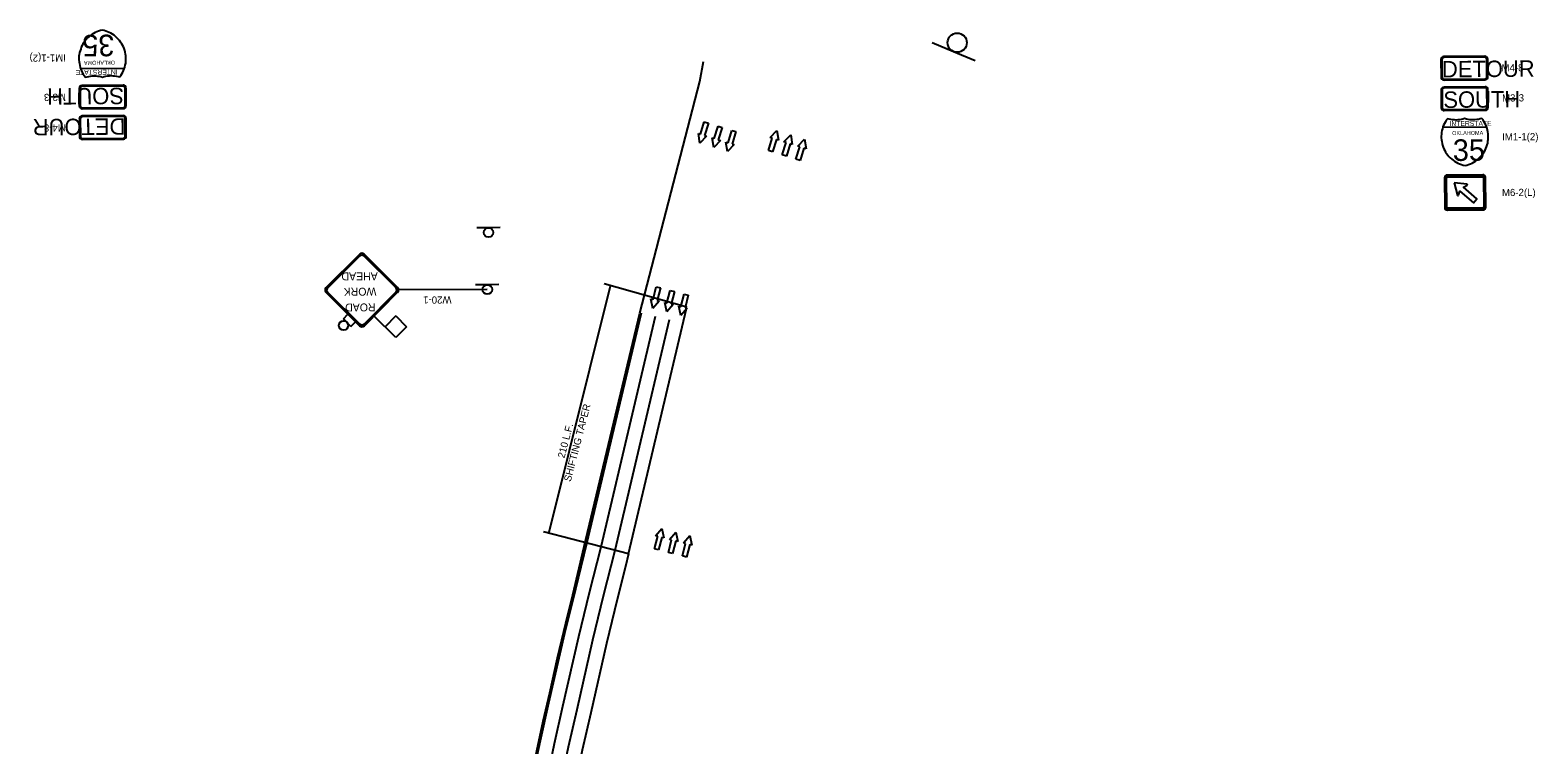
# Model space of a CAD drawing. Extents: x 2135767 to 2151731, y 141839 to 175894.
# Drawn here: x 2150475 to 2151731, y 147612 to 148208 of the extents above; entities that cross this region are included whole.
import ezdxf

# ---------------------------------------------------------------- set-up
doc = ezdxf.new("R2010")
doc.units = 0
for name, color, linetype in [('PR_Dimensions_Phase1', 7, 'Continuous'), ('PR_Phasing_Detour_1', 7, 'Continuous'), ('PR_Phasing_Traffic_Control_Devices_1', 7, 'Continuous'), ('PR_Phasing_Traffic_Striping_Dashed_Phase_1', 7, 'Continuous'), ('PR_Phasing_Traffic_Striping_White_Phase_1', 7, 'Continuous'), ('PR_Phasing_Traffic_Striping_Yellow_Phase_1', 7, 'Continuous'), ('Pr_Traffic_Arrows_Phase_1', 7, 'Continuous'), ('PR_Traffic_Striping_White_Temp', 7, 'Continuous'), ('PR_Txt', 7, 'Continuous'), ('PR_Txt_Phase_1', 7, 'Continuous')]:
    doc.layers.add(name, color=color, linetype=linetype)

# ---------------------------------------------------------------- blocks, each defined once
blk = doc.blocks.new('FLSHFLAG')
at = {"layer": 'PR_Txt'}
for p, q in [((-1.2, 14.13), (0.84, 16.15)), ((0.84, 16.15), (4.9, 12.08)), ((0.82, 12.08), (-1.2, 14.13)), ((0.82, 12.08), (2.86, 14.11)), ((9.26, 14), (8.4, 13.15)), ((9.26, 14), (10.68, 12.58)), ((10.68, 12.58), (9.83, 11.72))]:
    blk.add_line(p, q, dxfattribs=at)
blk.add_circle((10.65, 13.84), 0.873, dxfattribs=at)

msp = doc.modelspace()

# ---------------------------------------------------------------- linework, layer by layer
at = {"layer": 'PR_Dimensions_Phase1'}
for p, q in [((2150855.9, 147991.6), (2150782, 147991.3)), ((2150907.1, 147788.3), (2150958.6, 147994.6)), ((2151022.3, 147976.8), (2150953.3, 147996.3)), ((2150973.7, 147771.4), (2150902.7, 147789.6))]:
    msp.add_line(p, q, dxfattribs=at)
at = {"layer": 'PR_Phasing_Detour_1'}
for p, q in [((2151226.6, 148197.3), (2151244.5, 148189.9)), ((2151244.5, 148189.9), (2151262.3, 148182.5)), ((2151650.5, 148183.2), (2151650.6, 148168.6)), ((2151651.3, 148183.2), (2151651.4, 148168.6)), ((2151687.1, 148186), (2151652.9, 148185.7)), ((2151687.1, 148185.2), (2151652.9, 148184.9)), ((2151688.9, 148168.9), (2151688.8, 148183.5)), ((2151689.7, 148168.9), (2151689.6, 148183.5)), ((2150553.9, 148175.9), (2150516.7, 148175.6)), ((2151653.1, 148167), (2151687.3, 148167.2)), ((2151653.1, 148166.2), (2151687.3, 148166.4)), ((2150515.8, 148159.2), (2150515.9, 148144.5)), ((2150516.6, 148159.2), (2150516.8, 148144.5)), ((2150552.4, 148161.9), (2150518.2, 148161.7)), ((2150552.4, 148161.1), (2150518.3, 148160.8)), ((2150554.2, 148144.8), (2150554.1, 148159.5)), ((2150555, 148144.9), (2150554.9, 148159.5)), ((2151650.6, 148157.8), (2151650.8, 148143.1)), ((2151651.5, 148157.8), (2151651.6, 148143.1)), ((2151687.3, 148160.5), (2151653.1, 148160.2)), ((2151687.3, 148159.7), (2151653.1, 148159.4)), ((2151689, 148143.4), (2151688.9, 148158.1)), ((2151689.8, 148143.4), (2151689.7, 148158.1)), ((2150518.4, 148142.9), (2150552.6, 148143.2)), ((2150518.4, 148142.1), (2150552.6, 148142.4)), ((2151653.2, 148141.5), (2151687.4, 148141.8)), ((2151653.2, 148140.7), (2151687.4, 148141)), ((2150516, 148133.7), (2150516.1, 148119.1)), ((2150516.8, 148133.7), (2150516.9, 148119.1)), ((2150552.6, 148136.5), (2150518.4, 148136.2)), ((2150552.6, 148135.7), (2150518.4, 148135.4)), ((2150554.3, 148119.4), (2150554.2, 148134)), ((2150555.1, 148119.4), (2150555, 148134)), ((2151651.8, 148126.8), (2151689, 148127.1)), ((2150518.5, 148117.5), (2150552.7, 148117.7)), ((2150518.5, 148116.7), (2150552.7, 148116.9)), ((2151653.5, 148084.8), (2151653.7, 148059.8)), ((2151654.1, 148084.8), (2151654.3, 148059.8)), ((2151654.1, 148084.8), (2151654.3, 148059.8)), ((2151655.4, 148059.9), (2151655.2, 148084.8)), ((2151655.4, 148059.9), (2151655.2, 148084.8)), ((2151685.5, 148087.2), (2151655.7, 148087)), ((2151685.5, 148086.6), (2151655.7, 148086.4)), ((2151685.5, 148086.6), (2151655.7, 148086.4)), ((2151655.7, 148085.4), (2151685.5, 148085.6)), ((2151655.7, 148085.4), (2151685.5, 148085.6)), ((2151672.4, 148079.5), (2151661.5, 148080.6)), ((2151661.5, 148080.6), (2151664.2, 148070)), ((2151686.1, 148085.1), (2151686.3, 148060.1)), ((2151686.1, 148085.1), (2151686.3, 148060.1)), ((2151687.3, 148060.1), (2151687.1, 148085.1)), ((2151687.3, 148060.1), (2151687.1, 148085.1)), ((2151687.9, 148060.1), (2151687.7, 148085.1)), ((2151685.8, 148059.6), (2151655.9, 148059.3)), ((2151685.8, 148059.6), (2151655.9, 148059.3)), ((2151655.9, 148058.3), (2151685.8, 148058.5)), ((2151655.9, 148058.3), (2151685.8, 148058.5)), ((2151655.9, 148057.7), (2151685.8, 148057.9)), ((2150856.9, 148043.1), (2150847.3, 148043.1)), ((2150866.6, 148043.2), (2150856.9, 148043.1))]:
    msp.add_line(p, q, dxfattribs=at)
for points in [[(2150549.7, 148168.8), (2150550.6, 148170), (2150551.5, 148171.3), (2150552.2, 148172.7), (2150552.9, 148174.1), (2150553.4, 148175.6), (2150553.9, 148177), (2150554.3, 148178.6), (2150554.6, 148180.1), (2150554.8, 148181.6), (2150554.8, 148183.2), (2150554.8, 148184.7), (2150554.7, 148186.3), (2150554.5, 148187.8), (2150554.2, 148189.4), (2150553.8, 148190.9), (2150553.3, 148192.3), (2150552.7, 148193.8), (2150552, 148195.2), (2150551.2, 148196.5), (2150550.4, 148197.8), (2150549.4, 148199.1), (2150548.4, 148200.3), (2150547.3, 148201.4), (2150546.2, 148202.4), (2150544.9, 148203.4), (2150543.7, 148204.3), (2150542.3, 148205.1), (2150540.9, 148205.8), (2150539.5, 148206.4), (2150538.1, 148206.9), (2150536.6, 148207.4), (2150535, 148207.7), (2150533.5, 148207.3), (2150532, 148206.9), (2150530.6, 148206.3), (2150529.2, 148205.7), (2150527.8, 148204.9), (2150526.5, 148204.1), (2150525.2, 148203.2), (2150524, 148202.2), (2150522.9, 148201.2), (2150521.8, 148200), (2150520.8, 148198.8), (2150519.9, 148197.6), (2150519, 148196.3), (2150518.3, 148194.9), (2150517.6, 148193.5), (2150517.1, 148192), (2150516.6, 148190.6), (2150516.2, 148189.1), (2150515.9, 148187.5), (2150515.7, 148186), (2150515.6, 148184.4), (2150515.6, 148182.9), (2150515.8, 148181.3), (2150516, 148179.8), (2150516.3, 148178.2), (2150516.7, 148176.7), (2150517.2, 148175.3), (2150517.8, 148173.8), (2150518.4, 148172.4), (2150519.2, 148171.1), (2150520.1, 148169.8), (2150521, 148168.5), (2150522.4, 148168.9), (2150523.8, 148169.2), (2150525.3, 148169.5), (2150526.7, 148169.6), (2150528.2, 148169.7), (2150529.6, 148169.6), (2150531.1, 148169.5), (2150532.5, 148169.3), (2150534, 148169), (2150535.4, 148168.6), (2150536.8, 148169), (2150538.2, 148169.4), (2150539.6, 148169.6), (2150541.1, 148169.7), (2150542.5, 148169.8), (2150544, 148169.7), (2150545.4, 148169.6), (2150546.9, 148169.4), (2150548.3, 148169.1), (2150549.7, 148168.8)], [(2151655.9, 148133.9), (2151655, 148132.6), (2151654.2, 148131.3), (2151653.4, 148129.9), (2151652.8, 148128.5), (2151652.2, 148127.1), (2151651.7, 148125.6), (2151651.4, 148124.1), (2151651.1, 148122.5), (2151650.9, 148121), (2151650.8, 148119.4), (2151650.8, 148117.9), (2151650.9, 148116.3), (2151651.2, 148114.8), (2151651.5, 148113.3), (2151651.9, 148111.8), (2151652.4, 148110.3), (2151653, 148108.8), (2151653.7, 148107.4), (2151654.4, 148106.1), (2151655.3, 148104.8), (2151656.2, 148103.6), (2151657.2, 148102.4), (2151658.3, 148101.3), (2151659.5, 148100.2), (2151660.7, 148099.3), (2151662, 148098.4), (2151663.3, 148097.6), (2151664.7, 148096.9), (2151666.1, 148096.2), (2151667.6, 148095.7), (2151669.1, 148095.3), (2151670.6, 148094.9), (2151672.1, 148095.3), (2151673.6, 148095.7), (2151675.1, 148096.3), (2151676.5, 148096.9), (2151677.9, 148097.7), (2151679.2, 148098.5), (2151680.4, 148099.4), (2151681.6, 148100.4), (2151682.8, 148101.5), (2151683.9, 148102.6), (2151684.9, 148103.8), (2151685.8, 148105), (2151686.6, 148106.4), (2151687.4, 148107.7), (2151688, 148109.1), (2151688.6, 148110.6), (2151689.1, 148112.1), (2151689.5, 148113.6), (2151689.7, 148115.1), (2151689.9, 148116.6), (2151690, 148118.2), (2151690, 148119.8), (2151689.9, 148121.3), (2151689.7, 148122.9), (2151689.4, 148124.4), (2151689, 148125.9), (2151688.5, 148127.4), (2151687.9, 148128.8), (2151687.2, 148130.2), (2151686.4, 148131.5), (2151685.6, 148132.9), (2151684.7, 148134.1), (2151683.2, 148133.7), (2151681.8, 148133.4), (2151680.4, 148133.2), (2151678.9, 148133), (2151677.5, 148133), (2151676, 148133), (2151674.6, 148133.1), (2151673.1, 148133.3), (2151671.7, 148133.6), (2151670.3, 148134), (2151668.9, 148133.6), (2151667.5, 148133.3), (2151666, 148133), (2151664.6, 148132.9), (2151663.1, 148132.8), (2151661.7, 148132.9), (2151660.2, 148133), (2151658.8, 148133.2), (2151657.4, 148133.5), (2151655.9, 148133.9)], [(2151661.5, 148080.6), (2151664.2, 148070)], [(2151672.4, 148079.5), (2151661.5, 148080.6)], [(2151665.2, 148070.1), (2151666.4, 148073.6), (2151677.7, 148063.9), (2151680.4, 148067.1), (2151669.2, 148076.8), (2151672.5, 148078.5)], [(2151665.2, 148070.1), (2151666.4, 148073.6), (2151677.7, 148063.9), (2151680.4, 148067.1), (2151669.2, 148076.8), (2151672.5, 148078.5)]]:
    msp.add_lwpolyline(points, dxfattribs=at)
for centre, radius in [((2151247.5, 148197.3), 8), ((2150856.9, 148039.1), 4)]:
    msp.add_circle(centre, radius, dxfattribs=at)
for centre, radius, start, end in [((2151653, 148183.2), 2.44, 90.4611, 180.4611), ((2151653, 148183.2), 1.63, 90.4611, 180.4611), ((2151687.1, 148183.5), 2.44, 0.4611, 90.4611), ((2151687.1, 148183.5), 1.63, 0.4611, 90.4611), ((2151653.1, 148168.6), 2.44, 180.4611, 270.4611), ((2151653.1, 148168.6), 1.63, 180.4611, 270.4611), ((2151687.3, 148168.9), 2.44, 270.4611, 0.4611), ((2151687.3, 148168.9), 1.63, 270.4611, 0.4611), ((2150518.3, 148159.2), 2.44, 90.4611, 180.4611), ((2150518.3, 148159.2), 1.63, 90.4611, 180.4611), ((2150552.5, 148159.5), 2.44, 0.4611, 90.4611), ((2150552.5, 148159.5), 1.63, 0.4611, 90.4611), ((2151653.1, 148157.8), 2.44, 90.4611, 180.4611), ((2151653.1, 148157.8), 1.63, 90.4611, 180.4611), ((2151687.3, 148158.1), 2.44, 0.4611, 90.4611), ((2151687.3, 148158.1), 1.63, 0.4611, 90.4611), ((2150518.4, 148144.6), 2.44, 180.4611, 270.4611), ((2150518.4, 148144.6), 1.63, 180.4611, 270.4611), ((2150552.6, 148144.8), 2.44, 270.4611, 0.4611), ((2150552.6, 148144.8), 1.63, 270.4611, 0.4611), ((2151653.2, 148143.1), 2.44, 180.4611, 270.4611), ((2151653.2, 148143.1), 1.63, 180.4611, 270.4611), ((2151687.4, 148143.4), 1.63, 270.4611, 0.4611), ((2151687.4, 148143.4), 2.44, 270.4611, 0.4611), ((2150518.4, 148133.8), 2.44, 90.4611, 180.4611), ((2150518.4, 148133.8), 1.63, 90.4611, 180.4611), ((2150552.6, 148134), 2.44, 0.4611, 90.4611), ((2150552.6, 148134), 1.63, 0.4611, 90.4611), ((2150518.5, 148119.1), 2.44, 180.4611, 270.4611), ((2150518.5, 148119.1), 1.63, 180.4611, 270.4611), ((2150552.7, 148119.4), 2.44, 270.4611, 0.4611), ((2150552.7, 148119.4), 1.63, 270.4611, 0.4611), ((2151655.7, 148084.8), 2.16, 90.4611, 180.4611), ((2151655.7, 148084.8), 1.55, 90.4611, 180.4611), ((2151655.7, 148084.8), 1.55, 90.4611, 180.4611), ((2151655.7, 148084.8), 0.537, 90.4611, 180.4611), ((2151655.7, 148084.8), 0.537, 90.4611, 180.4611), ((2151671.9, 148078.9), 0.694, 319.2024, 49.2024), ((2151671.9, 148078.9), 0.694, 319.2024, 49.2024), ((2151685.5, 148085.1), 2.16, 0.4611, 90.4611), ((2151685.5, 148085.1), 1.55, 0.4611, 90.4611), ((2151685.5, 148085.1), 1.55, 0.4611, 90.4611), ((2151685.5, 148085.1), 0.537, 0.4611, 90.4611), ((2151685.5, 148085.1), 0.537, 0.4611, 90.4611), ((2151664.7, 148070.5), 0.694, 229.2024, 319.2024), ((2151664.7, 148070.5), 0.694, 229.2024, 319.2024), ((2151655.9, 148059.9), 2.16, 180.4611, 270.4611), ((2151655.9, 148059.9), 1.55, 180.4611, 270.4611), ((2151655.9, 148059.9), 1.55, 180.4611, 270.4611), ((2151655.9, 148059.9), 0.537, 180.4611, 270.4611), ((2151655.9, 148059.9), 0.537, 180.4611, 270.4611), ((2151685.7, 148060.1), 2.16, 270.4611, 0.4611), ((2151685.7, 148060.1), 1.55, 270.4611, 0.4611), ((2151685.7, 148060.1), 0.537, 270.4611, 0.4611), ((2151685.7, 148060.1), 1.55, 270.4611, 0.4611), ((2151685.7, 148060.1), 0.537, 270.4611, 0.4611)]:
    msp.add_arc(centre, radius, start, end, dxfattribs=at)
at = {"layer": 'PR_Phasing_Traffic_Control_Devices_1'}
for p, q in [((2150749.3, 148020.9), (2150721.5, 147993)), ((2150749.3, 148019.4), (2150723.1, 147993)), ((2150781.2, 147993.2), (2150753.2, 148021)), ((2150779.6, 147993.2), (2150753.2, 148019.4)), ((2150721.6, 147989), (2150749.5, 147961.3)), ((2150723.1, 147989), (2150749.5, 147962.9)), ((2150753.5, 147962.9), (2150779.6, 147989.3)), ((2150753.5, 147961.3), (2150781.2, 147989.3)), ((2150855.9, 147995.6), (2150846.2, 147995.6)), ((2150865.5, 147995.7), (2150855.9, 147995.6))]:
    msp.add_line(p, q, dxfattribs=at)
msp.add_circle((2150855.9, 147991.6), 4, dxfattribs=at)
for centre, start, end in [((2150751.3, 148019), 45.2355, 135.2355), ((2150751.3, 148017.4), 45.2355, 135.2355), ((2150723.5, 147991), 135.2355, 225.2355), ((2150725.1, 147991), 135.2355, 225.2355), ((2150777.6, 147991.2), 315.2355, 45.2355), ((2150779.2, 147991.2), 315.2355, 45.2355), ((2150751.5, 147964.9), 225.2355, 315.2355), ((2150751.5, 147963.3), 225.2355, 315.2355)]:
    msp.add_arc(centre, 2.81, start, end, dxfattribs=at)
at = {"layer": 'PR_Phasing_Traffic_Striping_Dashed_Phase_1'}
for points in [[(2150995.7, 147969.1), (2150950.4, 147776.9), (2150940.9, 147739), (2150932, 147702.1), (2150918.7, 147644.1), (2150911.7, 147613), (2150905.4, 147583.6), (2150886.7, 147494.2), (2150864.4, 147373), (2150848.5, 147279.4), (2150835.2, 147193.6), (2150823.3, 147104.9), (2150811.3, 147007.2), (2150800.8, 146902.2)], [(2151007.4, 147966.3), (2150962.1, 147774.1), (2150952.6, 147736.2), (2150943.6, 147699.4), (2150930.4, 147641.4), (2150923.4, 147610.4), (2150917.1, 147581.2), (2150898.5, 147491.9), (2150876.2, 147370.9), (2150860.4, 147277.4), (2150847.1, 147191.9), (2150835.2, 147103.3), (2150823.2, 147005.9), (2150812.7, 146901.1)]]:
    msp.add_lwpolyline(points, dxfattribs=at)
at = {"layer": 'PR_Phasing_Traffic_Striping_White_Phase_1'}
msp.add_lwpolyline([(2150844.1, 147330.9), (2150854.8, 147392.4), (2150859.3, 147416.9), (2150869.3, 147471.3), (2150885.1, 147550.1), (2150891.1, 147578.7), (2150902.6, 147631.8), (2150907.9, 147655.6), (2150914.5, 147684.7), (2150921.4, 147713.7), (2150927.1, 147737.3), (2150936.7, 147777.6), (2150983.1, 147972), (2151033, 148164.9), (2151036.1, 148181.7)], dxfattribs=at)
at = {"layer": 'PR_Phasing_Traffic_Striping_Yellow_Phase_1'}
msp.add_line((2150973.7, 147771.4), (2151022, 147975.8), dxfattribs=at)
msp.add_lwpolyline([(2150973.7, 147771.4), (2150971.1, 147760.7), (2150964.2, 147733.3), (2150955.3, 147696.6), (2150942.1, 147638.8), (2150935.1, 147607.9), (2150928.8, 147578.7), (2150910.3, 147489.6), (2150888, 147368.8), (2150872.2, 147275.5), (2150858.9, 147190.1), (2150847.1, 147101.8), (2150835.1, 147004.6), (2150824.7, 146899.9)], dxfattribs=at)
at = {"layer": 'Pr_Traffic_Arrows_Phase_1'}
for p, q in [((2151033.5, 148121), (2151036.7, 148131.3)), ((2151036.7, 148131.3), (2151040.1, 148130.2)), ((2151040.1, 148130.2), (2151037, 148119.9)), ((2151045, 148117.4), (2151048.2, 148127.8)), ((2151048.2, 148127.8), (2151051.6, 148126.7)), ((2151033.1, 148113.6), (2151031.8, 148121.5)), ((2151031.8, 148121.5), (2151033.5, 148121)), ((2151038.7, 148119.4), (2151033.1, 148113.6)), ((2151037, 148119.9), (2151038.7, 148119.4)), ((2151044.6, 148110), (2151043.3, 148118)), ((2151043.3, 148118), (2151045, 148117.4)), ((2151050.1, 148115.9), (2151044.6, 148110)), ((2151051.6, 148126.7), (2151048.4, 148116.4)), ((2151048.4, 148116.4), (2151050.1, 148115.9)), ((2151056, 148106.5), (2151054.7, 148114.4)), ((2151054.7, 148114.4), (2151056.5, 148113.9)), ((2151056.5, 148113.9), (2151059.6, 148124.2)), ((2151059.6, 148124.2), (2151063.1, 148123.2)), ((2151063.1, 148123.2), (2151059.9, 148112.8)), ((2151090.2, 148107.3), (2151093.4, 148117.6)), ((2151091.7, 148118.2), (2151097.3, 148124)), ((2151093.4, 148117.6), (2151091.7, 148118.2)), ((2151096.8, 148116.6), (2151093.6, 148106.3)), ((2151098.6, 148116), (2151096.8, 148116.6)), ((2151097.3, 148124), (2151098.6, 148116)), ((2151103.1, 148114.6), (2151108.7, 148120.4)), ((2151104.9, 148114.1), (2151103.1, 148114.6)), ((2151108.7, 148120.4), (2151110, 148112.5)), ((2151114.6, 148111), (2151120.2, 148116.8)), ((2151120.2, 148116.8), (2151121.5, 148108.9)), ((2151061.6, 148112.3), (2151056, 148106.5)), ((2151059.9, 148112.8), (2151061.6, 148112.3)), ((2151093.6, 148106.3), (2151090.2, 148107.3)), ((2151101.6, 148103.8), (2151104.9, 148114.1)), ((2151105.1, 148102.7), (2151101.6, 148103.8)), ((2151108.3, 148113), (2151105.1, 148102.7)), ((2151110, 148112.5), (2151108.3, 148113)), ((2151113.1, 148100.2), (2151116.3, 148110.5)), ((2151116.3, 148110.5), (2151114.6, 148111)), ((2151119.8, 148109.4), (2151116.5, 148099.1)), ((2151121.5, 148108.9), (2151119.8, 148109.4)), ((2151116.5, 148099.1), (2151113.1, 148100.2)), ((2150994, 147983.3), (2150996.7, 147993.8)), ((2150996.7, 147993.8), (2151000.2, 147992.9)), ((2151000.2, 147992.9), (2150997.5, 147982.4)), ((2151005.6, 147980.3), (2151008.3, 147990.8)), ((2151008.3, 147990.8), (2151011.8, 147989.9)), ((2151011.8, 147989.9), (2151009.1, 147979.4)), ((2150993.9, 147975.9), (2150992.2, 147983.8)), ((2150992.2, 147983.8), (2150994, 147983.3)), ((2150999.2, 147982), (2150993.9, 147975.9)), ((2150997.5, 147982.4), (2150999.2, 147982)), ((2151005.5, 147972.9), (2151003.9, 147980.8)), ((2151003.9, 147980.8), (2151005.6, 147980.3)), ((2151010.8, 147979), (2151005.5, 147972.9)), ((2151009.1, 147979.4), (2151010.8, 147979)), ((2151017.1, 147969.9), (2151015.5, 147977.8)), ((2151015.5, 147977.8), (2151017.2, 147977.3)), ((2151017.2, 147977.3), (2151019.9, 147987.8)), ((2151019.9, 147987.8), (2151023.4, 147986.9)), ((2151023.4, 147986.9), (2151020.7, 147976.4)), ((2151020.7, 147976.4), (2151022.4, 147976)), ((2151022.4, 147976), (2151017.1, 147969.9)), ((2150996.2, 147786.4), (2151001.4, 147792.5)), ((2151001.4, 147792.5), (2151003.1, 147784.6)), ((2151007.8, 147783.4), (2151013.1, 147789.5)), ((2151013.1, 147789.5), (2151014.8, 147781.7)), ((2150995.2, 147775.5), (2150997.9, 147786)), ((2150998.7, 147774.6), (2150995.2, 147775.5)), ((2150997.9, 147786), (2150996.2, 147786.4)), ((2151001.4, 147785.1), (2150998.7, 147774.6)), ((2151003.1, 147784.6), (2151001.4, 147785.1)), ((2151006.9, 147772.5), (2151009.5, 147783)), ((2151009.5, 147783), (2151007.8, 147783.4)), ((2151013, 147782.1), (2151010.3, 147771.6)), ((2151014.8, 147781.7), (2151013, 147782.1)), ((2151018.5, 147769.6), (2151021.2, 147780)), ((2151019.4, 147780.5), (2151024.7, 147786.6)), ((2151021.2, 147780), (2151019.4, 147780.5)), ((2151024.6, 147779.1), (2151022, 147768.7)), ((2151026.4, 147778.7), (2151024.6, 147779.1)), ((2151024.7, 147786.6), (2151026.4, 147778.7)), ((2151010.3, 147771.6), (2151006.9, 147772.5)), ((2151022, 147768.7), (2151018.5, 147769.6))]:
    msp.add_line(p, q, dxfattribs=at)
at = {"layer": 'PR_Traffic_Striping_White_Temp'}
msp.add_lwpolyline([(2150984.1, 147971.8), (2150938.7, 147779.6), (2150929.3, 147741.9), (2150920.3, 147704.9), (2150907, 147646.8), (2150899.9, 147615.6), (2150893.6, 147586.1), (2150874.9, 147496.5), (2150852.6, 147375.1), (2150841.9, 147312.1)], dxfattribs=at)

# ---------------------------------------------------------------- block references
at = {"layer": 'PR_Phasing_Traffic_Control_Devices_1', "xscale": 4.429125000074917, "yscale": 4.429125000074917, "rotation": -179.76450645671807}
msp.add_blockref('FLSHFLAG', (2150783.1, 148023.1), dxfattribs=at)

# ---------------------------------------------------------------- texts
at = {"layer": 'PR_Phasing_Detour_1'}
for s, height, rotation, p in [('35', 17.97, 180.4611, (2150545.1, 148204)), ('IM1-1(2)', 6, 180.4611, (2150504.8, 148187.6)), ('OKLAHOMA', 3.31, 180.4611, (2150545.7, 148182.3)), ('DETOUR', 13.68, 0.4611, (2151651.4, 148168.3)), ('M4-8', 6, 0.4611, (2151701, 148173.3)), ('INTERSTATE', 4.08, 180.4611, (2150547.9, 148174.8)), ('M3-3', 6, 180.4611, (2150504.8, 148154.8)), ('SOUTH', 13.68, 180.4611, (2150553.1, 148159.8)), ('SOUTH', 13.68, 0.4611, (2151652.6, 148142.9)), ('M3-3', 6, 0.4611, (2151701.5, 148148.2)), ('DETOUR', 13.68, 180.4611, (2150554.3, 148134.3)), ('M4-8', 6, 180.4611, (2150504.7, 148129.3)), ('INTERSTATE', 4.08, 0.4611, (2151657.7, 148127.8)), ('OKLAHOMA', 3.31, 0.4611, (2151659.9, 148120.3)), ('35', 17.97, 0.4611, (2151660.5, 148098.7)), ('IM1-1(2)', 6, 0.4611, (2151701.5, 148115.8)), ('M6-2(L)', 6, 0.4611, (2151701.4, 148069.4))]:
    msp.add_text(s, height=height, rotation=rotation, dxfattribs=at).set_placement(p)
at = {"layer": 'PR_Phasing_Traffic_Control_Devices_1'}
for s, p in [('AHEAD', (2150764.6, 148005.9)), ('WORK', (2150763.5, 147993.1)), ('ROAD', (2150762.8, 147980))]:
    msp.add_text(s, height=6.56, rotation=180.2355, dxfattribs=at).set_placement(p)
at = {"layer": 'PR_Txt_Phase_1'}
for s, rotation, p in [('W20-1', 180.3002, (2150826.1, 147985.9)), ('SHIFTING TAPER', 75.4783, (2150925.4, 147831.1)), ('210 L.F.', 75.4783, (2150920.2, 147850.7))]:
    msp.add_text(s, height=6, rotation=rotation, dxfattribs=at).set_placement(p)

doc.saveas('drawing.dxf')
